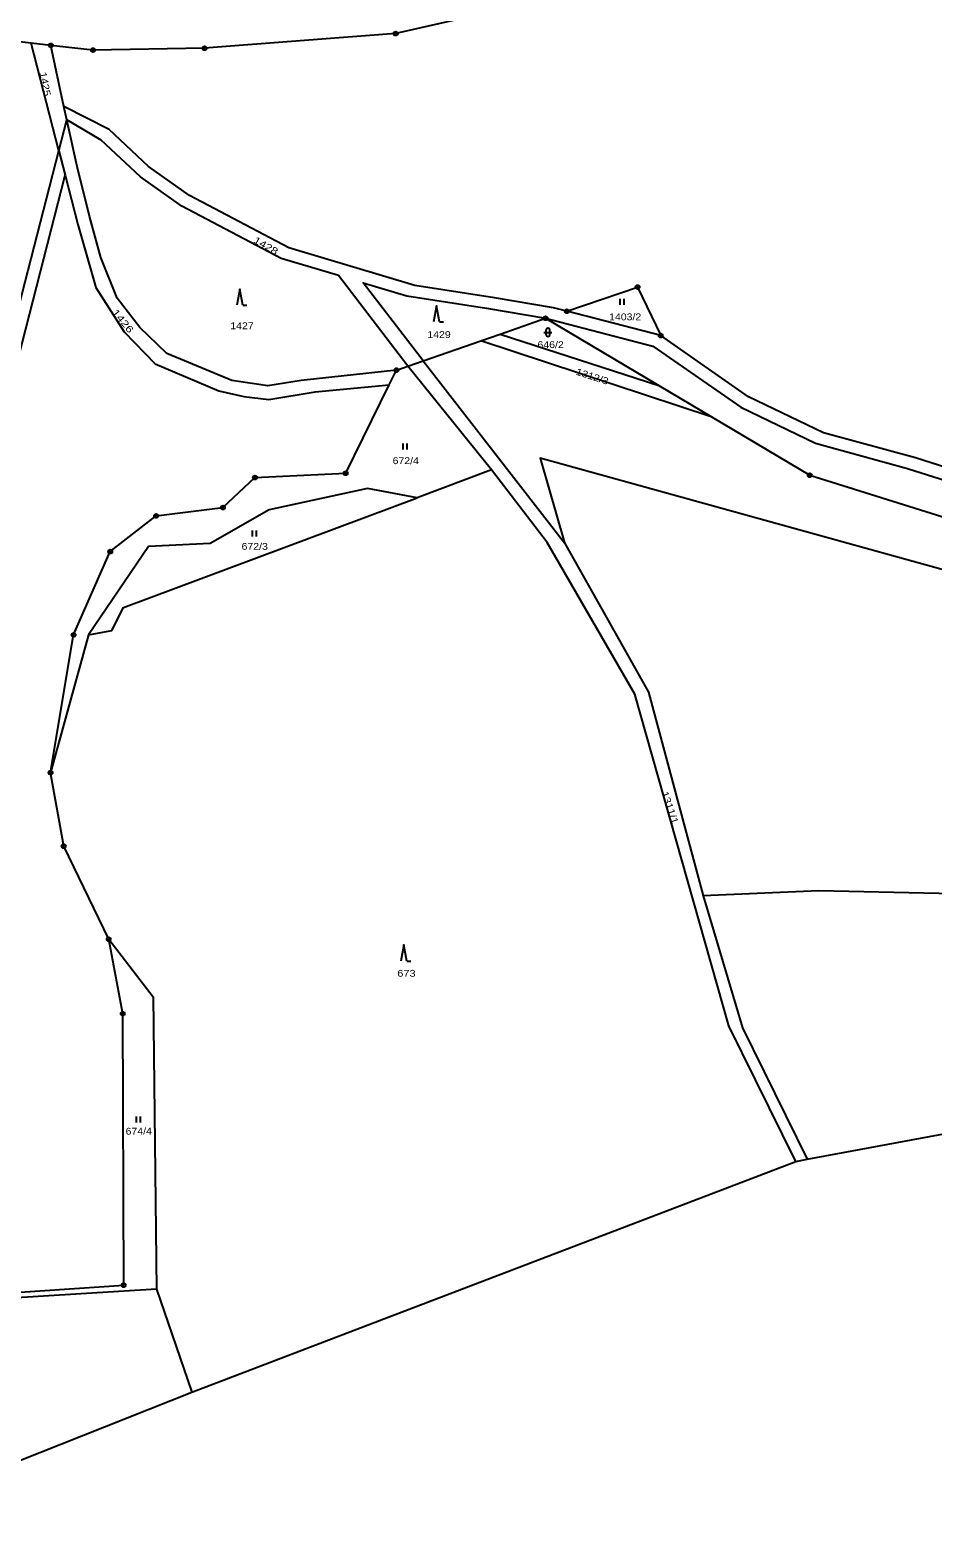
# Model space of a CAD drawing. Extents: x -872229 to -869198, y -1075981 to -1074329.
# Drawn here: x -870489.1 to -870264.6, y -1075867.9 to -1075493.1 of the extents above; entities that cross this region are included whole.
import ezdxf

# ---------------------------------------------------------------- set-up
doc = ezdxf.new("R2010")
doc.units = 0
doc.header["$LTSCALE"] = 0.68
for name, color, linetype, lineweight in [('1', 7, 'Continuous', 25), ('3', 7, 'Continuous', 25), ('8', 7, 'Continuous', 25)]:
    doc.layers.add(name, color=color, linetype=linetype, lineweight=lineweight)
doc.layers.add('2', color=7, linetype='Continuous')

msp = doc.modelspace()

# ---------------------------------------------------------------- linework, layer by layer
at = {"layer": '1'}
for p, q in [((-870483.95, -1075496.85), (-870488.89, -1075496.3)), ((-870481.98, -1075523.1), (-870479.99, -1075515.35)), ((-870481.98, -1075523.1), (-870480.43, -1075529.12)), ((-870332.25, -1075569.01), (-870355.62, -1075562.97)), ((-870372.22, -1075568.64), (-870332.73, -1075581.44)), ((-870319.49, -1075589.3), (-870376.98, -1075570.3)), ((-870395.16, -1075576.63), (-870391.35, -1075575.3)), ((-870391.35, -1075575.3), (-870356.17, -1075620.52)), ((-870397.97, -1075577.61), (-870395.16, -1075576.63)), ((-870374.35, -1075602.36), (-870395.16, -1075576.63)), ((-870374.35, -1075602.36), (-870392.86, -1075609.38)), ((-870474.58, -1075643.43), (-870484.04, -1075677.67)), ((-870448.9, -1075831.7), (-870298.63, -1075774.34)), ((-870298.63, -1075774.34), (-870295.8, -1075773.81)), ((-870540.14, -1075867.94), (-870448.9, -1075831.7))]:
    msp.add_line(p, q, dxfattribs=at)
for points in [[(-869861.67, -1075370.56), (-869878.14, -1075367.33), (-869908.77, -1075363.47), (-869918.42, -1075363.79), (-869963.81, -1075365.31), (-869991.44, -1075371.29), (-870013.06, -1075376.14), (-870080.98, -1075397.47), (-870137.41, -1075416.91), (-870198.36, -1075434.14), (-870229.56, -1075445.28), (-870312.6, -1075469.56), (-870365.19, -1075486.42), (-870398.17, -1075493.93), (-870445.72, -1075497.57), (-870473.49, -1075498.03), (-870483.95, -1075496.85)], [(-870495.74, -1075576.59), (-870481.98, -1075523.1), (-870488.89, -1075496.3), (-870505.74, -1075494.4)], [(-870479.99, -1075515.35), (-870480.69, -1075512.06), (-870483.95, -1075496.85)], [(-870355.62, -1075562.97), (-870358.95, -1075562.11), (-870373.64, -1075559.61), (-870393.44, -1075556.54), (-870424.74, -1075547.23), (-870449.44, -1075534.2), (-870459.66, -1075526.98), (-870469.46, -1075517.8), (-870480.69, -1075512.06)], [(-870397.97, -1075577.61), (-870421.72, -1075580.19), (-870430.01, -1075581.52), (-870438.98, -1075580.17), (-870455.07, -1075573.48), (-870461.84, -1075567.02), (-870467.43, -1075559.7), (-870471.56, -1075549.62), (-870474.38, -1075539.31), (-870477.41, -1075526.93), (-870479.99, -1075515.35)], [(-870395.16, -1075576.63), (-870412.38, -1075554.08), (-870426.7, -1075549.82), (-870451.4, -1075536.79), (-870461.62, -1075529.57), (-870471.42, -1075520.39), (-870479.99, -1075515.35)], [(-870557.85, -1075746.37), (-870540.19, -1075739.3), (-870505.25, -1075704.66), (-870498.26, -1075598.45), (-870480.43, -1075529.12)], [(-870480.43, -1075529.12), (-870477.28, -1075541.36), (-870472.81, -1075557.02), (-870465.71, -1075568.09), (-870457.97, -1075576.06), (-870442.16, -1075582.76), (-870435.93, -1075584.16), (-870429.7, -1075584.94), (-870418.23, -1075582.99), (-870399.77, -1075581.26), (-870397.97, -1075577.61)], [(-870391.35, -1075575.3), (-870406.3, -1075555.89), (-870395.38, -1075559.14), (-870375.6, -1075562.2), (-870360.91, -1075564.7)], [(-870355.62, -1075562.97), (-870338.02, -1075556.95), (-870332.25, -1075569.01)], [(-870391.35, -1075575.3), (-870376.98, -1075570.3), (-870372.22, -1075568.64), (-870360.91, -1075564.7), (-870332.73, -1075581.44), (-870319.49, -1075589.3)], [(-870360.91, -1075564.7), (-870334.21, -1075571.6), (-870312.37, -1075586.81), (-870293.77, -1075595.76), (-870270.86, -1075602.02), (-870243.34, -1075610.77), (-870217.09, -1075618.71), (-870179.15, -1075630.08), (-870157.97, -1075632.03), (-870128.13, -1075632.63), (-870114.57, -1075631.72), (-870098.39, -1075625.25), (-870092.04, -1075619.77), (-870087.29, -1075619.63), (-870052.6, -1075626.97), (-870018.4, -1075625.53), (-869988.87, -1075627.77), (-869967.84, -1075631.16), (-869962.49, -1075632.97), (-869956.97, -1075636.94), (-869956.21, -1075634.42)], [(-869956.21, -1075634.42), (-869961.39, -1075630.69), (-869968.14, -1075628.41), (-869989.17, -1075625.02), (-870018.7, -1075622.78), (-870052.9, -1075624.22), (-870087.59, -1075616.88), (-870093.16, -1075617.33), (-870100.3, -1075623.21), (-870115.61, -1075629.33), (-870126.17, -1075630.04), (-870156.01, -1075629.44), (-870177.19, -1075627.49), (-870215.13, -1075616.12), (-870241.38, -1075608.18), (-870268.9, -1075599.43), (-870291.81, -1075593.17), (-870310.41, -1075584.22), (-870332.25, -1075569.01)], [(-870484.04, -1075677.67), (-870478.31, -1075643.42), (-870469.17, -1075622.73), (-870457.77, -1075613.84), (-870441.15, -1075611.76), (-870433.18, -1075604.3), (-870410.61, -1075603.25), (-870399.77, -1075581.26)], [(-870319.49, -1075589.3), (-870295.19, -1075603.73), (-870207.28, -1075631.27), (-870168.61, -1075639.64), (-870121.56, -1075638.1), (-870072.83, -1075635.74), (-870016.23, -1075634.96), (-869958.54, -1075642.14), (-869957.53, -1075638.79), (-869956.97, -1075636.94)], [(-870298.63, -1075774.34), (-870315.32, -1075740.66), (-870338.68, -1075658.18), (-870360.47, -1075620.46), (-870374.35, -1075602.36)], [(-869946.97, -1075719.04), (-869951.52, -1075667.78), (-870006.44, -1075655.77), (-870192.84, -1075646.38), (-870362.26, -1075599.45), (-870356.17, -1075620.52)], [(-870392.86, -1075609.38), (-870405.2, -1075607.04), (-870429.66, -1075612.36), (-870444.32, -1075620.68), (-870459.63, -1075621.47), (-870474.58, -1075643.43)], [(-870474.58, -1075643.43), (-870468.78, -1075642.35), (-870465.87, -1075636.59), (-870392.86, -1075609.38)], [(-870356.17, -1075620.52), (-870335.29, -1075657.65), (-870321.66, -1075708.31)], [(-870469.57, -1075719.09), (-870480.77, -1075695.96), (-870484.04, -1075677.67)], [(-870179.01, -1075751.24), (-870188.98, -1075726.65), (-870204.4, -1075708.79), (-870263.11, -1075707.73), (-870292.9, -1075707.03), (-870321.66, -1075708.31)], [(-870321.66, -1075708.31), (-870311.88, -1075741.09), (-870295.8, -1075773.81)], [(-870531.01, -1075809.47), (-870465.83, -1075805.11), (-870466.06, -1075737.62), (-870469.57, -1075719.09)], [(-870469.57, -1075719.09), (-870458.47, -1075733.44), (-870457.7, -1075806.11), (-870448.9, -1075831.7)], [(-870295.8, -1075773.81), (-870199.13, -1075755.85), (-870179.01, -1075751.24)], [(-870457.7, -1075806.11), (-870531.41, -1075810.63), (-870556.01, -1075813.08)]]:
    msp.add_lwpolyline(points, dxfattribs=at)
at = {"layer": '3'}
for p, q in [((-870436.22, -1075561.46), (-870435.224, -1075561.46)), ((-870342.311, -1075561.35), (-870342.311, -1075559.85)), ((-870341.31, -1075561.35), (-870341.31, -1075559.85)), ((-870387.27, -1075565.62), (-870386.274, -1075565.62)), ((-870361.311, -1075568.201), (-870359.309, -1075568.201)), ((-870360.811, -1075567.701), (-870360.811, -1075568.702)), ((-870359.809, -1075568.702), (-870359.809, -1075567.701)), ((-870396.311, -1075597.36), (-870396.311, -1075595.86)), ((-870395.31, -1075597.36), (-870395.31, -1075595.86)), ((-870433.781, -1075618.96), (-870433.781, -1075617.46)), ((-870432.78, -1075618.96), (-870432.78, -1075617.46)), ((-870395.41, -1075724.53), (-870394.414, -1075724.53)), ((-870462.621, -1075764.65), (-870462.621, -1075763.15)), ((-870461.62, -1075764.65), (-870461.62, -1075763.15))]:
    msp.add_line(p, q, dxfattribs=at)
for points in [[(-870436.22, -1075561.46), (-870436.97, -1075557.46), (-870437.72, -1075561.46)], [(-870387.27, -1075565.62), (-870388.02, -1075561.62), (-870388.77, -1075565.62)], [(-870395.41, -1075724.53), (-870396.16, -1075720.53), (-870396.91, -1075724.53)]]:
    msp.add_lwpolyline(points, dxfattribs=at)
for centre, start, end in [((-870360.31, -1075567.7009), 0, 180), ((-870360.31, -1075568.7009), 180, 359.98789)]:
    msp.add_arc(centre, 0.5, start, end, dxfattribs=at)
at = {"layer": '8'}
for centre, radius in [((-870398.17, -1075493.9299), 0.5), ((-870398.17, -1075493.9299), 0.0303), ((-870483.95, -1075496.8499), 0.5), ((-870483.95, -1075496.8499), 0.0303), ((-870473.49, -1075498.0299), 0.5), ((-870445.72, -1075497.5699), 0.5), ((-870445.72, -1075497.5699), 0.0303), ((-870473.49, -1075498.0299), 0.0303), ((-870338.02, -1075556.9499), 0.5), ((-870338.02, -1075556.9499), 0.0303), ((-870360.91, -1075564.6999), 0.5), ((-870360.91, -1075564.6999), 0.0303), ((-870355.62, -1075562.9699), 0.5), ((-870355.62, -1075562.9699), 0.0303), ((-870332.25, -1075569.0099), 0.5), ((-870332.25, -1075569.0099), 0.0303), ((-870397.97, -1075577.6099), 0.5), ((-870397.97, -1075577.6099), 0.0303), ((-870433.18, -1075604.2999), 0.5), ((-870433.18, -1075604.2999), 0.0303), ((-870410.61, -1075603.2499), 0.5), ((-870410.61, -1075603.2499), 0.0303), ((-870295.19, -1075603.7299), 0.5), ((-870295.19, -1075603.7299), 0.0303), ((-870457.77, -1075613.8399), 0.5), ((-870457.77, -1075613.8399), 0.0303), ((-870441.15, -1075611.7599), 0.5), ((-870441.15, -1075611.7599), 0.0303), ((-870469.17, -1075622.7299), 0.5), ((-870469.17, -1075622.7299), 0.0303), ((-870478.31, -1075643.4199), 0.5), ((-870478.31, -1075643.4199), 0.0303), ((-870484.04, -1075677.6699), 0.5), ((-870484.04, -1075677.6699), 0.0303), ((-870480.77, -1075695.9599), 0.5), ((-870480.77, -1075695.9599), 0.0303), ((-870469.57, -1075719.0899), 0.5), ((-870469.57, -1075719.0899), 0.0303), ((-870466.06, -1075737.6199), 0.5), ((-870466.06, -1075737.6199), 0.0303), ((-870465.83, -1075805.1099), 0.5), ((-870465.83, -1075805.1099), 0.0303)]:
    msp.add_circle(centre, radius, dxfattribs=at)

# ---------------------------------------------------------------- texts
at = {"layer": '2'}
for s, rotation, width, p in [('1425', 281, 1.2, (-870486.764, -1075503.652)), ('1428', 330, 1.3, (-870433.735, -1075545.746)), ('1426', 309, 1.35, (-870468.84, -1075563.264)), ('1312/3', 342, 1.2, (-870353.512, -1075578.678)), ('1311/1', 289, 1.2, (-870332.103, -1075682.686))]:
    msp.add_text(s, height=1.7, rotation=rotation, dxfattribs=dict(at, width=width)).set_placement(p)
for s, width, p in [('1403/2', 1.15, (-870345.1, -1075565.2)), ('1427', 1.15, (-870439.32, -1075567.42)), ('1429', 1.15, (-870390.31, -1075569.61)), ('646/2', 1.15, (-870362.91, -1075572.12)), ('672/4', 1.15, (-870398.95, -1075600.97)), ('672/3', 1.15, (-870436.52, -1075622.27)), ('673', 1.2, (-870397.78, -1075728.43)), ('674/4', 1.15, (-870465.37, -1075767.68))]:
    msp.add_text(s, height=1.7, dxfattribs=dict(at, width=width)).set_placement(p)

doc.saveas('drawing.dxf')
